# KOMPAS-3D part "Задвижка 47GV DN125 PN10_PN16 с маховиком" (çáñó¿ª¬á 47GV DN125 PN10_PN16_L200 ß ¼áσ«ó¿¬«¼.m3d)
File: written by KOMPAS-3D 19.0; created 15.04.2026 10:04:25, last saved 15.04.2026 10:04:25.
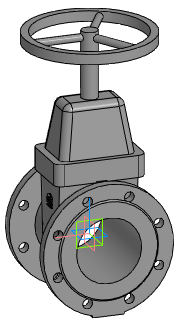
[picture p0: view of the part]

Document properties: Автор: Евгений; Полное имя файла: Z:\3.Личные\kachalov\3d для проектировщиков\2.1 Тип 47GV, 47GV.Z\Задвижка 47GV_DN40-DN600\stp_Задвижка 47GV\Задвижка 47GV DN125 PN10_PN16_L200 с маховиком.m3d

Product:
- Part/product: Задвижка 47GV DN125 PN10_PN16 с маховиком

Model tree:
1. Операция без истории:1  (labels: Задвижка 47GV DN125 PN10_PN16 с маховиком)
